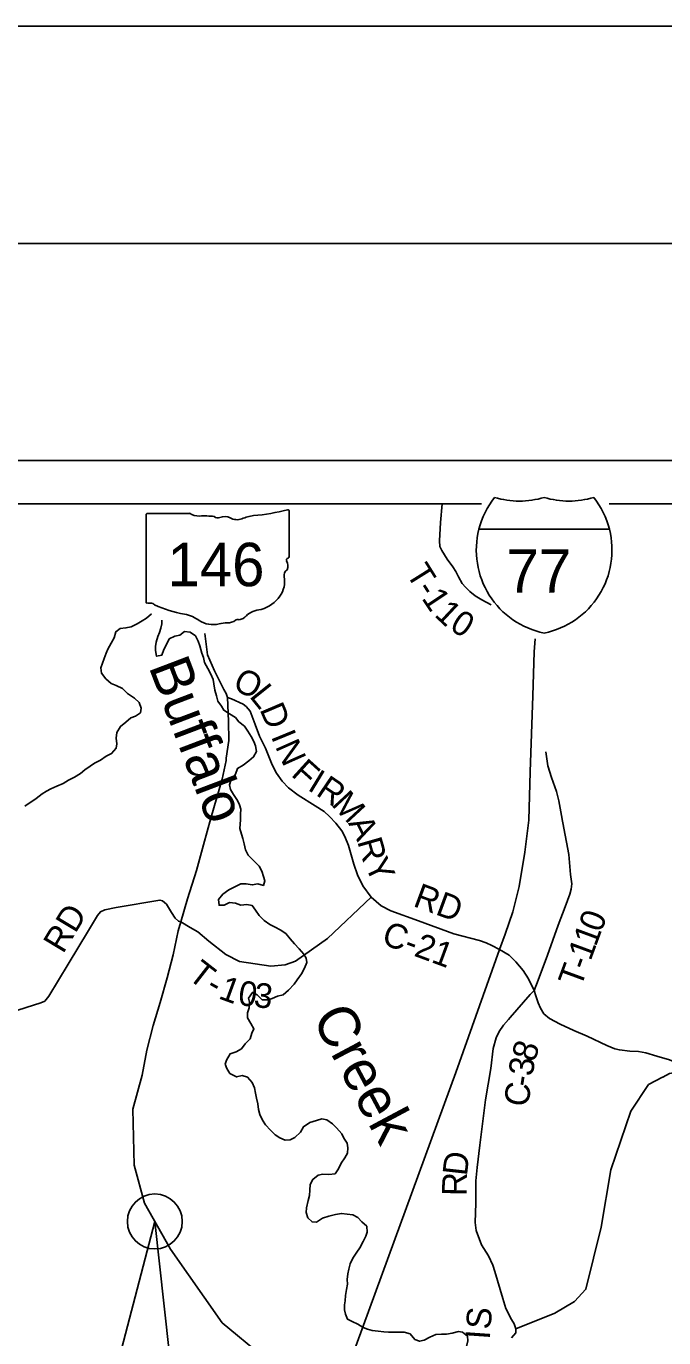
# Model space of a CAD drawing. Extents: x -22 to 431, y -18 to 160.
# Drawn here: x 3.384 to 4.852, y 18.98 to 22 of the extents above; entities that cross this region are included whole.
import ezdxf

# ---------------------------------------------------------------- set-up
doc = ezdxf.new("R2010")
doc.units = 0
for name, color, linetype in [('GM_X_Adjacent_County', 7, 'Continuous'), ('GM_X_Adjacent_County_Text', 7, 'Continuous'), ('GM_X_Airport_Location_Class_2', 7, 'Continuous'), ('GM_X_Airport_Text_Class_2', 7, 'Continuous'), ('GM_X_City_Street', 7, 'Continuous'), ('GM_X_City_Street_Text', 7, 'Continuous'), ('GM_X_County', 7, 'Continuous'), ('GM_X_County_Road', 7, 'Continuous'), ('GM_X_Minor_Lake', 7, 'Continuous'), ('GM_X_Minor_River', 7, 'Continuous'), ('GM_X_Minor_River_Text', 7, 'Continuous'), ('GM_X_Rail_Line', 7, 'Continuous'), ('GM_X_Rail_Line_Text', 7, 'Continuous'), ('GM_X_Section', 7, 'Continuous'), ('GM_X_Township', 7, 'Continuous')]:
    doc.layers.add(name, color=color, linetype=linetype)

msp = doc.modelspace()

# ---------------------------------------------------------------- linework, layer by layer
at = {"layer": 'GM_X_Adjacent_County'}
msp.add_circle((3.6797, 19.2474), 0.0633, dxfattribs=at)
at = {"layer": 'GM_X_Adjacent_County_Text'}
for points in [[(3.8471, 20.4541), (3.8565, 20.451), (3.8828, 20.4386), (3.8903, 20.4332), (3.8993, 20.4229), (3.9107, 20.3917), (3.921, 20.365), (3.9343, 20.3372), (3.9502, 20.2988), (3.9602, 20.2797), (3.9729, 20.2618), (3.9878, 20.2461), (4.01, 20.2288), (4.0491, 20.2046), (4.0693, 20.1915), (4.0817, 20.1804), (4.0967, 20.1647), (4.1105, 20.1471), (4.1175, 20.1338), (4.1256, 20.1132), (4.1381, 20.0703), (4.1465, 20.0459), (4.1587, 20.0204), (4.1777, 19.9944), (4.2006, 19.9741), (4.2235, 19.9629), (4.2868, 19.9399), (4.3685, 19.9095), (4.4274, 19.8942), (4.4424, 19.8891), (4.456, 19.8829), (4.4736, 19.8739), (4.4955, 19.8609), (4.5112, 19.8456), (4.528, 19.8257), (4.5399, 19.8063), (4.5529, 19.7796)], [(4.5529, 19.7796), (4.5437, 19.7702), (4.4978, 19.7168), (4.494, 19.7125)], [(4.5529, 19.7796), (4.5573, 19.7674), (4.5628, 19.7507), (4.5679, 19.7385), (4.5754, 19.7259), (4.5885, 19.7148), (4.6129, 19.7021), (4.6442, 19.6874), (4.675, 19.6742), (4.7206, 19.6529), (4.7386, 19.6451), (4.7496, 19.6424), (4.7734, 19.6399), (4.7934, 19.6385), (4.8104, 19.6357), (4.8356, 19.6282), (4.865, 19.6196), (4.8823, 19.6123), (4.8925, 19.6076), (4.8994, 19.6032), (4.9062, 19.5958), (4.9138, 19.5877), (4.9169, 19.5778), (4.9197, 19.5689)], [(4.494, 19.7125), (4.4939, 19.7123), (4.4829, 19.6996), (4.4729, 19.6852), (4.4656, 19.6705), (4.4585, 19.6456), (4.4531, 19.5998), (4.4409, 19.5277), (4.4284, 19.4231), (4.422, 19.3718), (4.4192, 19.3407), (4.4185, 19.2898), (4.4174, 19.2454), (4.42, 19.2269), (4.4319, 19.1934), (4.4479, 19.1682), (4.4581, 19.1464), (4.4625, 19.1325), (4.469, 19.1117), (4.481, 19.0702), (4.4883, 19.0468), (4.5008, 19.022), (4.5074, 19.0119), (4.5109, 19.0002), (4.5108, 18.9907), (4.5008, 18.9792)]]:
    msp.add_lwpolyline(points, dxfattribs=at)
at = {"layer": 'GM_X_Airport_Location_Class_2'}
for p, q in [((3.6594, 20.8748), (3.6594, 20.6747)), ((3.6594, 20.6747), (3.6594, 20.8748)), ((3.6594, 20.6747), (3.6594, 20.8748)), ((3.6627, 20.8782), (3.7592, 20.8782)), ((3.989, 20.8832), (3.989, 20.7785)), ((3.989, 20.7785), (3.989, 20.7785))]:
    msp.add_line(p, q, dxfattribs=at)
for centre, major_axis, start_param, end_param in [((3.6632, 20.8752), (0.00382, 0), 1.712693, 3.28349), ((3.7822, 20.9015), (0.037, 0), 4.042523, 4.731795), ((3.7945, 20.7659), (0.133, 0), 1.404758, 1.657858), ((3.8403, 20.8531), (0.0222, 0), 0.950623, 2.079405), ((3.9162, 20.8171), (0.0703, 0), 1.699011, 2.107814), ((3.8716, 21.1511), (0.3495, 0), 4.814394, 5.042369), ((3.9854, 20.8836), (0.00367, 0), 6.141152, 7.989035), ((3.8247, 20.8763), (0.0107, 0), 3.836095, 5.185415), ((3.869, 20.8849), (0.0267, 0), 4.081561, 5.145723), ((3.9882, 20.7708), (0.00568, 0), 1.883978, 3.671073), ((3.952, 20.7576), (0.0341, 0), 5.934695, 6.695948), ((3.9851, 20.7781), (0.00393, 0), 5.05454, 6.418171), ((3.8912, 20.7214), (0.0874, 0), 5.101752, 6.440018), ((4.0022, 20.7347), (0.0248, 0), 2.387724, 3.262537), ((3.6632, 20.6742), (0.00385, 0), 3.00124, 4.508301), ((3.6638, 20.6947), (0.0294, 0), 4.665946, 4.897461), ((3.6698, 20.6631), (0.0106, 0), 0.519207, 1.627899), ((3.8037, 20.8429), (0.2524, 0), 4.195997, 4.488961), ((3.7284, 20.5848), (0.079, 0), 0.823519, 1.323587), ((3.8138, 20.6621), (0.0501, 0), 4.026481, 4.996735), ((3.8464, 20.6472), (0.0267, 0), 4.691044, 5.507374), ((3.8706, 20.6278), (0.00752, 0), 1.147584, 2.315152), ((3.8674, 20.6553), (0.0282, 0), 4.937069, 5.64225), ((3.9281, 20.6185), (0.0479, 0), 1.647645, 2.488434), ((3.8428, 20.593), (0.0412, 0), 1.495662, 1.94098)]:
    msp.add_ellipse(centre, major_axis=major_axis, ratio=0.8, start_param=start_param, end_param=end_param, dxfattribs=at)
at = {"layer": 'GM_X_County'}
msp.add_lwpolyline([(0, 0), (34, 0), (34, 22), (0, 22)], close=True, dxfattribs=at)
at = {"layer": 'GM_X_County_Road'}
msp.add_lwpolyline([(4.8489, 19.5795), (4.8164, 19.5625), (4.7758, 19.5018), (4.73, 19.3667), (4.7077, 19.2344), (4.6723, 19.0915), (4.6463, 19.0629), (4.6005, 19.0359), (4.5109, 19.0002)], dxfattribs=at)
at = {"layer": 'GM_X_Minor_Lake'}
msp.add_lwpolyline([(3.5763, 18.8501), (3.6797, 19.2474), (3.7232, 18.8501)], close=True, dxfattribs=at)
at = {"layer": 'GM_X_Minor_River'}
for points in [[(3.672, 20.6471), (3.6607, 20.6371), (3.6508, 20.6307), (3.6387, 20.6235), (3.6255, 20.6167), (3.613, 20.6144), (3.5998, 20.6129), (3.5899, 20.6054), (3.5857, 20.5917), (3.5793, 20.5792), (3.5713, 20.5656), (3.5679, 20.5561), (3.5629, 20.544), (3.5591, 20.5334), (3.5557, 20.5224), (3.5568, 20.5099), (3.5666, 20.4974), (3.5791, 20.486), (3.5908, 20.4814), (3.6052, 20.475), (3.6169, 20.4636), (3.6327, 20.4529), (3.6433, 20.4423), (3.6486, 20.4298), (3.647, 20.4188), (3.6349, 20.4112), (3.6247, 20.4075), (3.6126, 20.3972), (3.6005, 20.3874), (3.5921, 20.3734), (3.591, 20.3601), (3.5921, 20.3476), (3.5909, 20.3374), (3.5803, 20.3253), (3.5678, 20.3192), (3.5546, 20.3101), (3.5409, 20.303), (3.5311, 20.2961), (3.5182, 20.2874), (3.5084, 20.2787), (3.4944, 20.2708), (3.4807, 20.2636), (3.469, 20.2564), (3.4542, 20.2496), (3.4402, 20.244), (3.43, 20.2387), (3.4202, 20.2322), (3.4062, 20.2216), (3.38, 20.2042)], [(3.696, 20.6323), (3.6955, 20.6238), (3.6935, 20.6139), (3.6901, 20.6041), (3.6863, 20.5946), (3.6829, 20.5814), (3.681, 20.5719), (3.681, 20.562), (3.6836, 20.5491), (3.6957, 20.5514), (3.7006, 20.5643), (3.7067, 20.5764), (3.7128, 20.5889), (3.7256, 20.5957), (3.7374, 20.5976), (3.7484, 20.6059), (3.7608, 20.6044), (3.7733, 20.596), (3.7793, 20.5835), (3.7835, 20.5729), (3.788, 20.5562), (3.7914, 20.546), (3.794, 20.535), (3.8019, 20.5209), (3.8087, 20.508), (3.8143, 20.4955), (3.8154, 20.4853), (3.8177, 20.4709), (3.8214, 20.458), (3.8248, 20.4455), (3.8335, 20.4341), (3.8384, 20.4246), (3.8516, 20.4166), (3.8656, 20.4079), (3.8735, 20.3984), (3.886, 20.3878), (3.8939, 20.3764), (3.9018, 20.3643), (3.9075, 20.3529), (3.9116, 20.343), (3.9138, 20.3301), (3.907, 20.3172), (3.896, 20.3085), (3.8831, 20.2983), (3.8703, 20.2908), (3.8653, 20.2775), (3.8547, 20.2631), (3.8517, 20.2533), (3.8543, 20.2423), (3.8611, 20.2305), (3.8698, 20.2172), (3.875, 20.2066), (3.878, 20.1968), (3.8773, 20.1854), (3.8772, 20.1725), (3.8761, 20.1623), (3.8757, 20.1524)], [(3.8757, 20.1524), (3.8794, 20.1395), (3.8824, 20.1297), (3.8851, 20.1171), (3.8884, 20.1035), (3.8949, 20.091), (3.9201, 20.0655), (3.9258, 20.0538), (3.9299, 20.042), (3.9333, 20.0318), (3.9299, 20.0212), (3.917, 20.025), (3.9042, 20.0224), (3.8902, 20.0247), (3.8777, 20.0247), (3.8637, 20.0179), (3.8501, 20.0114), (3.8364, 20.0012), (3.8266, 19.9887), (3.8277, 19.9758), (3.839, 19.9762), (3.8519, 19.9819), (3.8651, 19.9803), (3.878, 19.9758), (3.8912, 19.9773), (3.9041, 19.975), (3.9116, 19.9644), (3.9199, 19.9522), (3.9312, 19.9405), (3.9448, 19.9313), (3.9569, 19.9249), (3.9686, 19.9188), (3.9811, 19.9104), (3.9917, 19.8987), (4.0011, 19.8865), (4.012, 19.8751), (4.0226, 19.863), (4.0283, 19.8535), (4.0298, 19.844), (4.0241, 19.8304), (4.0176, 19.8175), (4.0077, 19.8039), (4.0005, 19.7937), (3.9873, 19.7804), (3.9752, 19.7694), (3.9623, 19.7664), (3.9498, 19.7608), (3.94, 19.7577), (3.9271, 19.7581), (3.9154, 19.7691), (3.9045, 19.7748), (3.8957, 19.7616), (3.898, 19.7521), (3.8968, 19.7392), (3.8934, 19.7282), (3.8934, 19.7165), (3.9005, 19.7032), (3.9077, 19.6907), (3.9031, 19.6808), (3.899, 19.668), (3.888, 19.6566), (3.8792, 19.6449), (3.8668, 19.6384), (3.8535, 19.6335), (3.8444, 19.6188), (3.8417, 19.6093), (3.8455, 19.5994), (3.8527, 19.5881)], [(3.8527, 19.5881), (3.868, 19.5804), (3.8805, 19.5835), (3.8934, 19.5801), (3.9036, 19.5676), (3.909, 19.5551), (3.9113, 19.5426), (3.9136, 19.5313), (3.917, 19.5184), (3.9186, 19.5051), (3.9213, 19.4938), (3.9274, 19.4809), (3.9342, 19.4703), (3.946, 19.4575), (3.957, 19.4473), (3.9673, 19.4397), (3.9801, 19.4348), (3.9915, 19.4356), (4.0021, 19.4406), (4.0149, 19.4528), (4.0217, 19.4657), (4.0368, 19.4752), (4.0523, 19.4798), (4.0641, 19.4836), (4.0758, 19.4818), (4.0887, 19.4723), (4.0982, 19.4629), (4.11, 19.4489), (4.1149, 19.4391), (4.1229, 19.4274), (4.1241, 19.4171), (4.123, 19.4046), (4.117, 19.394), (4.1087, 19.3814), (4.1023, 19.3685), (4.0947, 19.3575), (4.08, 19.3556), (4.0667, 19.3563), (4.0561, 19.3543), (4.0436, 19.3441), (4.0372, 19.3323), (4.0365, 19.3198), (4.0358, 19.3069), (4.0328, 19.2959), (4.0291, 19.2792), (4.028, 19.2678), (4.0318, 19.2561), (4.0417, 19.2463), (4.0519, 19.2459), (4.0659, 19.2554), (4.0802, 19.2597), (4.0958, 19.2631), (4.1094, 19.2658), (4.1226, 19.2644), (4.1359, 19.2625), (4.1469, 19.2565)], [(4.1469, 19.2565), (4.1564, 19.2463), (4.1681, 19.2365), (4.1686, 19.2228), (4.1656, 19.2133), (4.1595, 19.2012), (4.1516, 19.1868), (4.1445, 19.1769), (4.1358, 19.1628), (4.1298, 19.1495), (4.1264, 19.1374), (4.1242, 19.1271), (4.1227, 19.1135), (4.1231, 19.1033), (4.1209, 19.0911), (4.119, 19.0771), (4.1179, 19.065), (4.1168, 19.0555), (4.1161, 19.0441), (4.1191, 19.0343), (4.1237, 19.0221), (4.134, 19.0173), (4.1469, 19.0112), (4.1598, 19.0033), (4.1696, 18.9996), (4.1802, 18.9966), (4.1942, 18.9947), (4.2067, 18.9932)], [(4.2067, 18.9932), (4.2177, 18.9925), (4.2438, 18.9926), (4.2541, 18.9923), (4.2673, 18.9889), (4.2787, 18.9753), (4.2893, 18.9715), (4.2999, 18.9739), (4.3128, 18.9807), (4.3268, 18.9868), (4.34, 18.988), (4.351, 18.9881), (4.3646, 18.9904), (4.3786, 18.9938), (4.3885, 18.9927), (4.3999, 18.9833), (4.4007, 18.9723), (4.3973, 18.9598), (4.3909, 18.9469)]]:
    msp.add_lwpolyline(points, dxfattribs=at)
at = {"layer": 'GM_X_Minor_River_Text'}
for points in [[(4.4541, 20.6673), (4.4326, 20.6792), (4.4176, 20.6885), (4.4049, 20.6981), (4.3948, 20.7084), (4.3877, 20.7168), (4.3787, 20.7321), (4.3728, 20.7443), (4.3657, 20.7553), (4.3531, 20.7729), (4.3404, 20.7927), (4.336, 20.8019), (4.3353, 20.8152), (4.3373, 20.8572), (4.3414, 20.9)], [(4.6179, 20.1736), (4.6098, 20.2162), (4.6044, 20.2378), (4.593, 20.2702), (4.5845, 20.2971), (4.5799, 20.329)], [(4.5529, 19.7796), (4.5622, 19.803), (4.5839, 19.8608), (4.6088, 19.9296), (4.6244, 19.9719), (4.6356, 20.0013), (4.6384, 20.0127), (4.6396, 20.0248), (4.6372, 20.0464), (4.6328, 20.0923), (4.6195, 20.1653), (4.618, 20.1732), (4.6179, 20.1736)], [(3.3472, 19.7288), (3.4173, 19.7508), (3.4264, 19.7549), (3.4356, 19.7666), (3.4798, 19.8397), (3.5267, 19.9174), (3.5475, 19.9524), (3.5544, 19.9603), (3.5646, 19.9648), (3.5904, 19.9702), (3.6915, 19.9874), (3.6975, 19.9858), (3.7062, 19.9782), (3.7177, 19.9587), (3.7266, 19.9461), (3.7345, 19.9388), (3.7393, 19.9374)], [(3.7393, 19.9374), (3.7608, 19.9246), (3.7785, 19.9145), (3.8043, 19.8927), (3.843, 19.8624), (3.8746, 19.8461), (3.9466, 19.8355), (3.98, 19.8383), (4.0035, 19.8471), (4.0773, 19.8991), (4.1777, 19.9944)], [(4.9062, 19.5958), (4.8798, 19.5908), (4.8652, 19.588), (4.8492, 19.5797), (4.8489, 19.5795)]]:
    msp.add_lwpolyline(points, dxfattribs=at)
at = {"layer": 'GM_X_Rail_Line'}
for points in [[(3.795, 20.6014), (3.7955, 20.5952), (3.8013, 20.5523), (3.8173, 20.5157), (3.8259, 20.4983), (3.8385, 20.4727), (3.8441, 20.4632), (3.8471, 20.4541), (3.8495, 20.3995), (3.8499, 20.3553), (3.8443, 20.3143), (3.8442, 20.3141)], [(4.1161, 18.8885), (4.3732, 19.5907), (4.4736, 19.8739), (4.4861, 19.9094), (4.5039, 19.9608), (4.5185, 20.019), (4.5321, 20.0981), (4.5409, 20.1714), (4.5437, 20.2826), (4.5498, 20.4578), (4.5529, 20.5591), (4.5554, 20.5894)], [(3.8442, 20.3141), (3.8436, 20.3093), (3.835, 20.2664), (3.8084, 20.1765), (3.7921, 20.1149), (3.7758, 20.0559), (3.755, 19.9908), (3.7393, 19.9374), (3.7331, 19.9166), (3.722, 19.8614), (3.7083, 19.8082), (3.6923, 19.7519), (3.6762, 19.6989), (3.6614, 19.6419), (3.6503, 19.5845), (3.6289, 19.5062), (3.6323, 19.3773), (3.6558, 19.2894), (3.7159, 19.1839), (3.8344, 19.0142), (3.9274, 18.937)]]:
    msp.add_lwpolyline(points, dxfattribs=at)
at = {"layer": 'GM_X_Rail_Line_Text'}
for p, q in [((4.4259, 20.8416), (4.7265, 20.8416)), ((4.7265, 20.8416), (4.4259, 20.8416)), ((4.7265, 20.8416), (4.4259, 20.8416))]:
    msp.add_line(p, q, dxfattribs=at)
for centre, start, end in [((4.6153, 20.7937), 141.669, 165.8066), ((4.5191, 21.1017), 253.0091, 286.9909), ((4.6333, 21.1017), 253.0091, 286.9909), ((4.5371, 20.7937), 14.1934, 38.331), ((4.6153, 20.7937), 165.8066, 258.463), ((4.5371, 20.7937), 281.537, 14.1934)]:
    msp.add_arc(centre, 0.1953, start, end, dxfattribs=at)
at = {"layer": 'GM_X_Section'}
for p, q in [((2, 21), (9, 21)), ((2.1, 20.9), (4.4317, 20.9)), ((4.7256, 20.9), (8.9, 20.9))]:
    msp.add_line(p, q, dxfattribs=at)
at = {"layer": 'GM_X_Township'}
msp.add_lwpolyline([(1.5, 21.5), (33.5, 21.5), (33.5, 0.5), (1.5, 0.5)], close=True, dxfattribs=at)

# ---------------------------------------------------------------- texts
at = {"layer": 'GM_X_Airport_Location_Class_2'}
for s, p in [('146', (3.709, 20.7104)), ('77', (4.4895, 20.6953))]:
    msp.add_text(s, height=0.1, dxfattribs=at).set_placement(p)
at = {"layer": 'GM_X_Airport_Text_Class_2'}
for s, rotation, p in [('Buffalo', 290.7843, (3.6647, 20.5256)), ('Creek', 298.0991, (4.0403, 19.7164))]:
    msp.add_text(s, height=0.09468, rotation=rotation, dxfattribs=at).set_placement(p)
at = {"layer": 'GM_X_City_Street'}
for s, height, rotation, p in [('O', 0.0568, 333.2183, (3.8561, 20.4751)), ('L', 0.0568, 308.7421, (3.8958, 20.4566)), ('D', 0.0568, 293.013, (3.9203, 20.427)), ('I', 0.0568, 292.2949, (3.9464, 20.3649)), ('N', 0.0568, 294.0168, (3.956, 20.3416)), ('F', 0.0568, 317.8384, (3.9914, 20.2752)), ('I', 0.0568, 328.6139, (4.0291, 20.2425)), ('R', 0.0568, 325.7882, (4.0484, 20.2308)), ('M', 0.0568, 312.863, (4.0845, 20.2067)), ('A', 0.0568, 296.6433, (4.124, 20.165)), ('R', 0.0568, 286.0151, (4.1454, 20.1229)), ('Y', 0.0568, 295.5868, (4.1619, 20.0684)), ('RD', 0.05682, 339.725, (4.2721, 19.9744)), ('C-21', 0.05682, 339.725, (4.199, 19.8876)), ('8', 0.0568, 72.1493, (4.5539, 19.6124)), ('3', 0.0568, 82.7498, (4.5501, 19.5804)), ('-', 0.0568, 80.9845, (4.5461, 19.5554)), ('C', 0.0568, 80.5787, (4.5384, 19.509)), ('D', 0.0568, 83.7366, (4.3985, 19.351)), ('R', 0.0568, 88.9774, (4.3977, 19.3057)), ('S', 0.0568, 85.4814, (4.4526, 18.9976)), ('I', 0.0568, 86.0564, (4.451, 18.9745))]:
    msp.add_text(s, height=height, rotation=rotation, dxfattribs=at).set_placement(p)
at = {"layer": 'GM_X_City_Street_Text'}
for s, height, rotation, p in [('T', 0.0568, 302.0376, (4.2568, 20.7401)), ('1', 0.0568, 303.6961, (4.2927, 20.6829)), ('-', 0.0568, 302.2305, (4.2794, 20.7039)), ('1', 0.0568, 316.8619, (4.3213, 20.6429)), ('0', 0.0568, 327.46, (4.3559, 20.612)), ('RD', 0.05682, 58.8678, (3.4683, 19.8621)), ('0', 0.0568, 69.3148, (4.7072, 19.9111)), ('1', 0.0568, 69.7381, (4.6951, 19.8784)), ('1', 0.0568, 69.8039, (4.683, 19.8456)), ('T', 0.0568, 322.1521, (3.7531, 19.8086)), ('T', 0.0568, 69.8206, (4.6603, 19.7838)), ('-', 0.0568, 69.8121, (4.675, 19.8237)), ('-', 0.0568, 330.6706, (3.7943, 19.7775)), ('1', 0.0568, 339.9706, (3.8238, 19.7618)), ('0', 0.0568, 352.1052, (3.8694, 19.7467)), ('3', 0.0568, 353.9545, (3.906, 19.7416))]:
    msp.add_text(s, height=height, rotation=rotation, dxfattribs=at).set_placement(p)

doc.saveas('drawing.dxf')
